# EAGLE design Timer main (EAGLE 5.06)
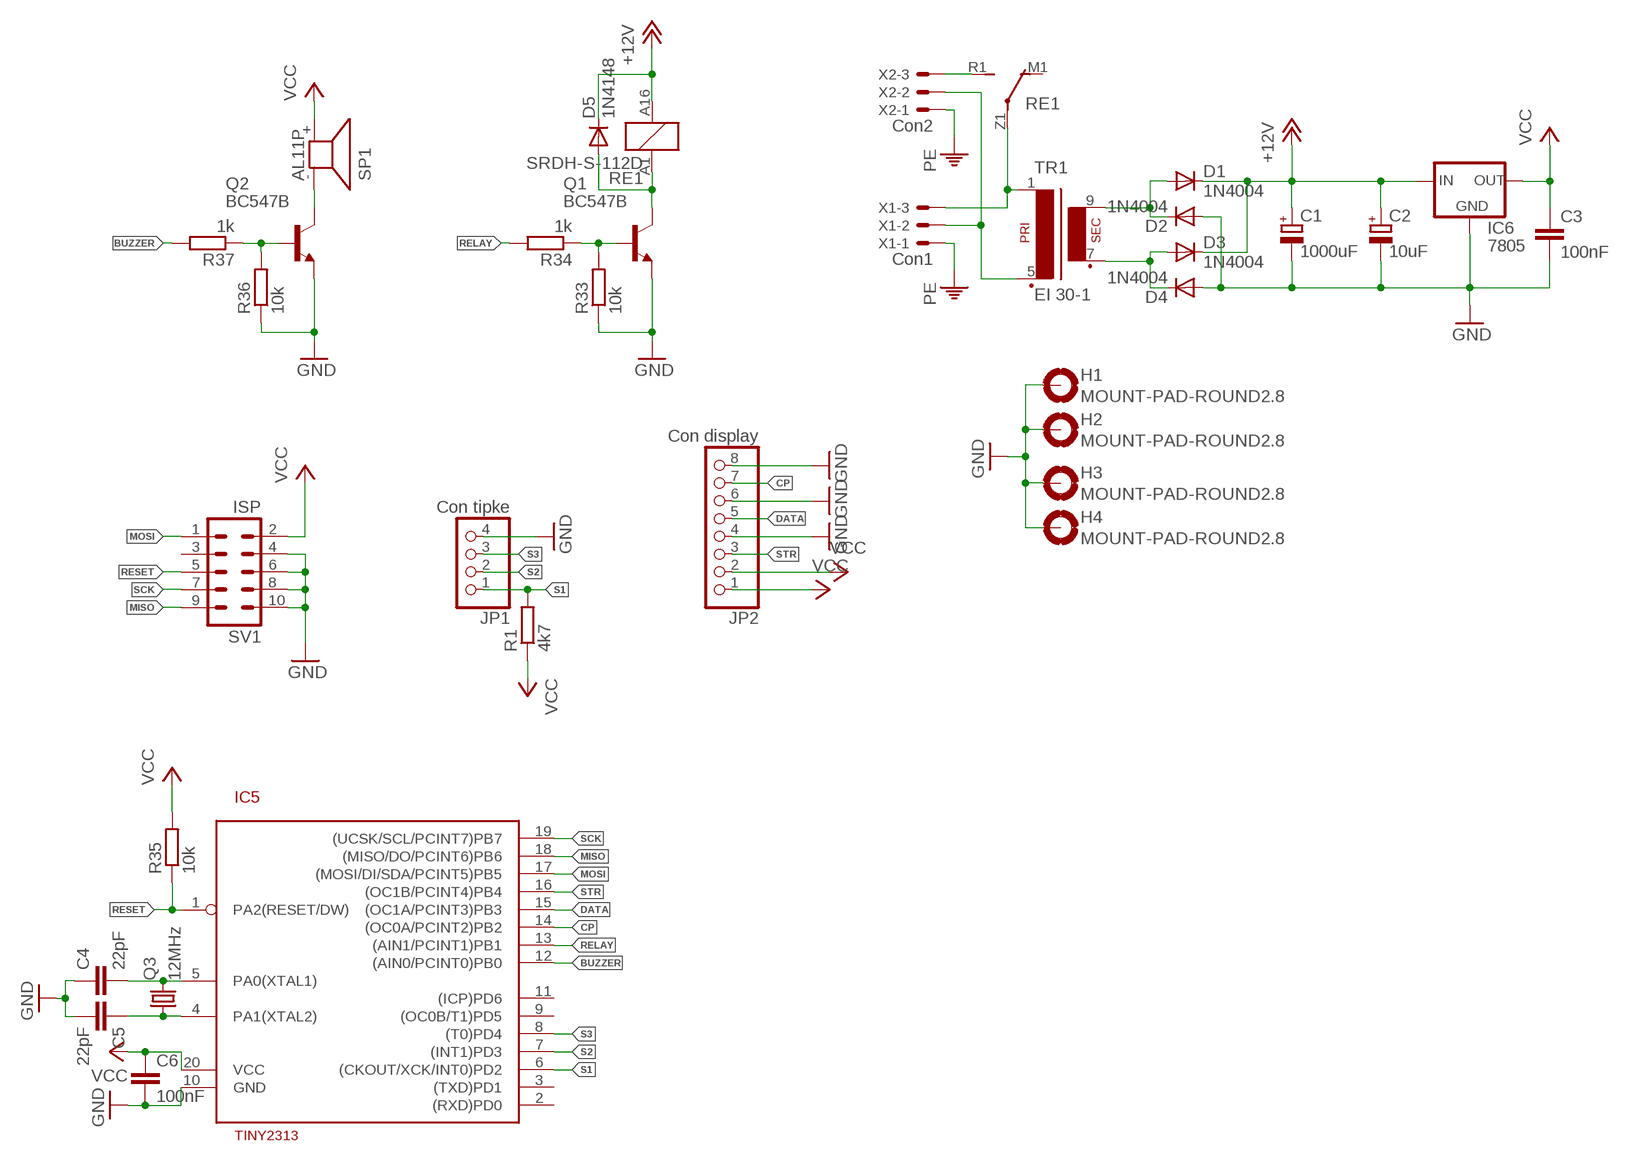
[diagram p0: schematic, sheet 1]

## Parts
C1  1000uF  CPOL-EUTT5D10  [TT5D10]
C2  10uF  CPOL-EUE2.5-5  [E2,5-5]
C3  100nF  C-EU050-025X075  [C050-025X075]
C4  22pF  C-EU025-025X050  [C025-025X050]
C5  22pF  C-EU025-025X050  [C025-025X050]
C6  100nF  C-EU050-025X075  [C050-025X075]
D1  1N4004  [DO41-10]
D2  1N4004  [DO41-10]
D3  1N4004  [DO41-10]
D4  1N4004  [DO41-10]
D5  1N4148  1N4148DO35-10  [DO35-10]
H1  MOUNT-PAD-ROUND2.8  [2,8-PAD]
H2  MOUNT-PAD-ROUND2.8  [2,8-PAD]
H3  MOUNT-PAD-ROUND2.8  [2,8-PAD]
H4  MOUNT-PAD-ROUND2.8  [2,8-PAD]
IC5  TINY2313  [DIL20]
IC6  7805  78XXL  [78XXL]
JP1  Con tipke  PINHD-1X4  [1X04]
JP2  Con display  PINHD-1X8  [1X08]
Q1  BC547B  [TO92]
Q2  BC547B  [TO92]
Q3  12MHz  CRYSTALHC49S  [HC49/S]
R1  4k7  R-EU_0207/10  [0207/10]
R33  10k  R-EU_0207/10  [0207/10]
R34  1k  R-EU_0207/10  [0207/10]
R35  10k  R-EU_0207/10  [0207/10]
R36  10k  R-EU_0207/10  [0207/10]
R37  1k  R-EU_0207/10  [0207/10]
RE1  SRDH-S-112D  [SRDH-S-112D]
SP1  AL11P  [AL11P]
SV1  ISP  ML10  [ML10]
TR1  EI 30-1  EI30-1-L  [SAMOZICE]
X1  Con1  KK-156-3  [KK-156-3]
X2  Con2  KK-156-3  [KK-156-3]

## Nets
+12V: C1.+ C2.+ D1.C D3.C D5.C IC6.IN RE1.A16
BUZZER: IC5.12((AIN0/PCINT0)PB0) R37.2
CP: IC5.14((OC0A/PCINT2)PB2) JP2.7
DATA: IC5.15((OC1A/PCINT3)PB3) JP2.5
GND: C1.- C2.- C3.2 C4.1 C5.2 C6.2 D2.A D4.A H1.B2,8(MOUNT) H2.B2,8(MOUNT) H3.B2,8(MOUNT) H4.B2,8(MOUNT) IC5.10(GND) IC6.GND JP1.4 JP2.4 JP2.6 JP2.8 Q1.1(E) Q2.1(E) R33.1 R36.1 SV1.4 SV1.6 SV1.8 SV1.10
MISO: IC5.18((MISO/DO/PCINT6)PB6) SV1.9
MOSI: IC5.17((MOSI/DI/SDA/PCINT5)PB5) SV1.1
N$65: RE1.Z1(P) TR1.1 X1.3
N$69: TR1.5(P2) X1.2 X2.2
N$70: D1.A D2.C TR1.9(S4)
N$71: D3.A D4.C TR1.7(S3)
N$72: RE1.R1(S) X2.3
N$73: Q1.2(B) R33.2 R34.1
N$74: D5.A Q1.3(C) RE1.A1
N$76: C4.2 IC5.5(PA0(XTAL1)) Q3.2
N$77: C5.1 IC5.4(PA1(XTAL2)) Q3.1
N$78: Q2.2(B) R36.2 R37.1
N$79: Q2.3(C) SP1.-
PE: X1.1 X2.1
RELAY: IC5.13((AIN1/PCINT1)PB1) R34.2
RESET: IC5.1(PA2(RESET/DW)) R35.1 SV1.5
S1: IC5.6((CKOUT/XCK/INT0)PD2) JP1.1 R1.2
S2: IC5.7((INT1)PD3) JP1.2
S3: IC5.8((T0)PD4) JP1.3
SCK: IC5.19((UCSK/SCL/PCINT7)PB7) SV1.7
STR: IC5.16((OC1B/PCINT4)PB4) JP2.3
VCC: C3.1 C6.1 IC5.20(VCC) IC6.OUT JP2.1 JP2.2 R1.1 R35.2 SP1.+ SV1.2
Unconnected: IC5.2((RXD)PD0) IC5.3((TXD)PD1) IC5.9((OC0B/T1)PD5) IC5.11((ICP)PD6) RE1.M1(O) SV1.3

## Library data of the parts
C1 C2 = resistor:CPOL-EU: POLARIZED CAPACITOR, European symbol
C3-C6 = resistor:C-EU: CAPACITOR, European symbol
D1-D4 = diode:1N4004: DIODE
D5 = diode:1N4148: DIODE
H1-H4 = holes:MOUNT-PAD-ROUND: MOUNTING PAD, round
IC5 = atmel:TINY2313: 2kB Flash, 20-pin
IC6 = v-reg:78XXL: VOLTAGE REGULATOR
JP1 = pinhead:PINHD-1X4: PIN HEADER
JP2 = pinhead:PINHD-1X8: PIN HEADER
Q1 Q2 = transistor-npn:BC547*: NPN Transistor
Q3 = crystal:CRYSTAL: CRYSTAL
R1 R33-R37 = resistor:R-EU_: RESISTOR, European symbol
RE1 = relay:SRDH-S-112D: 24V, 10A relay
SP1 = buzzer:AL11P: SPEAKER
SV1 = con-harting-ml:ML10: HARTING
TR1 = trafo:EI30-1: TRANSFORMER 1 primary winding, 1 secondary winding ERA
X1 X2 = con-molex:KK-156-3: KK 156 HEADER Source: http://www.molex.com/pdm_docs/sd/026604100_sd.pdf

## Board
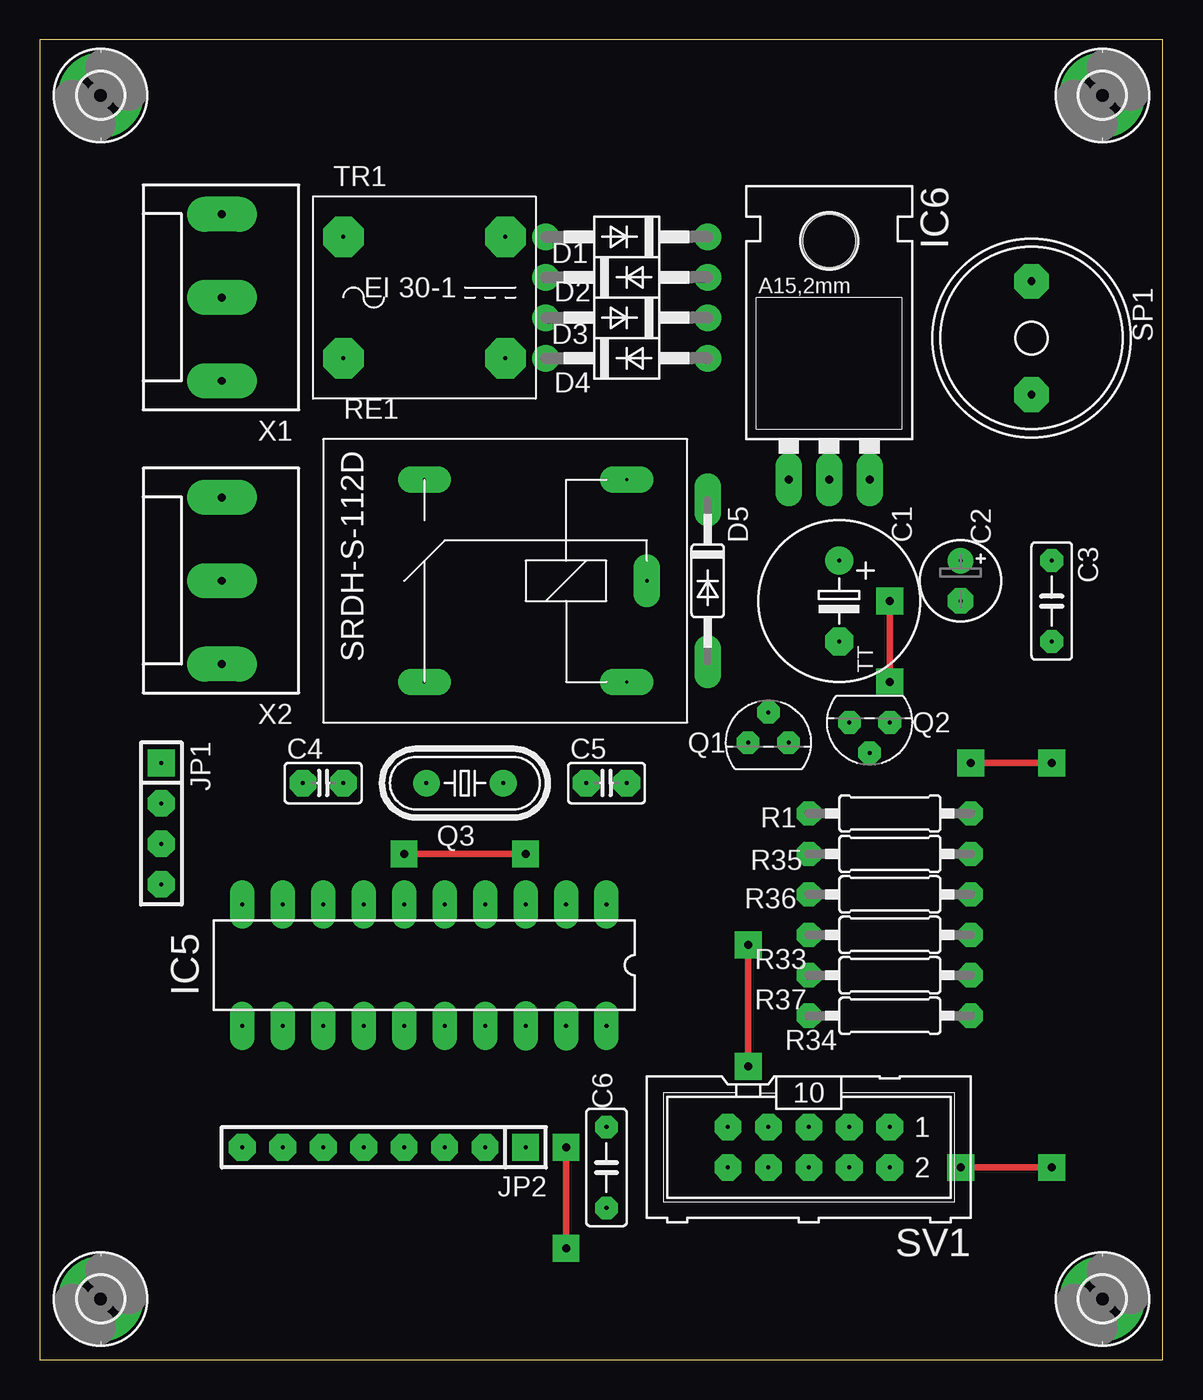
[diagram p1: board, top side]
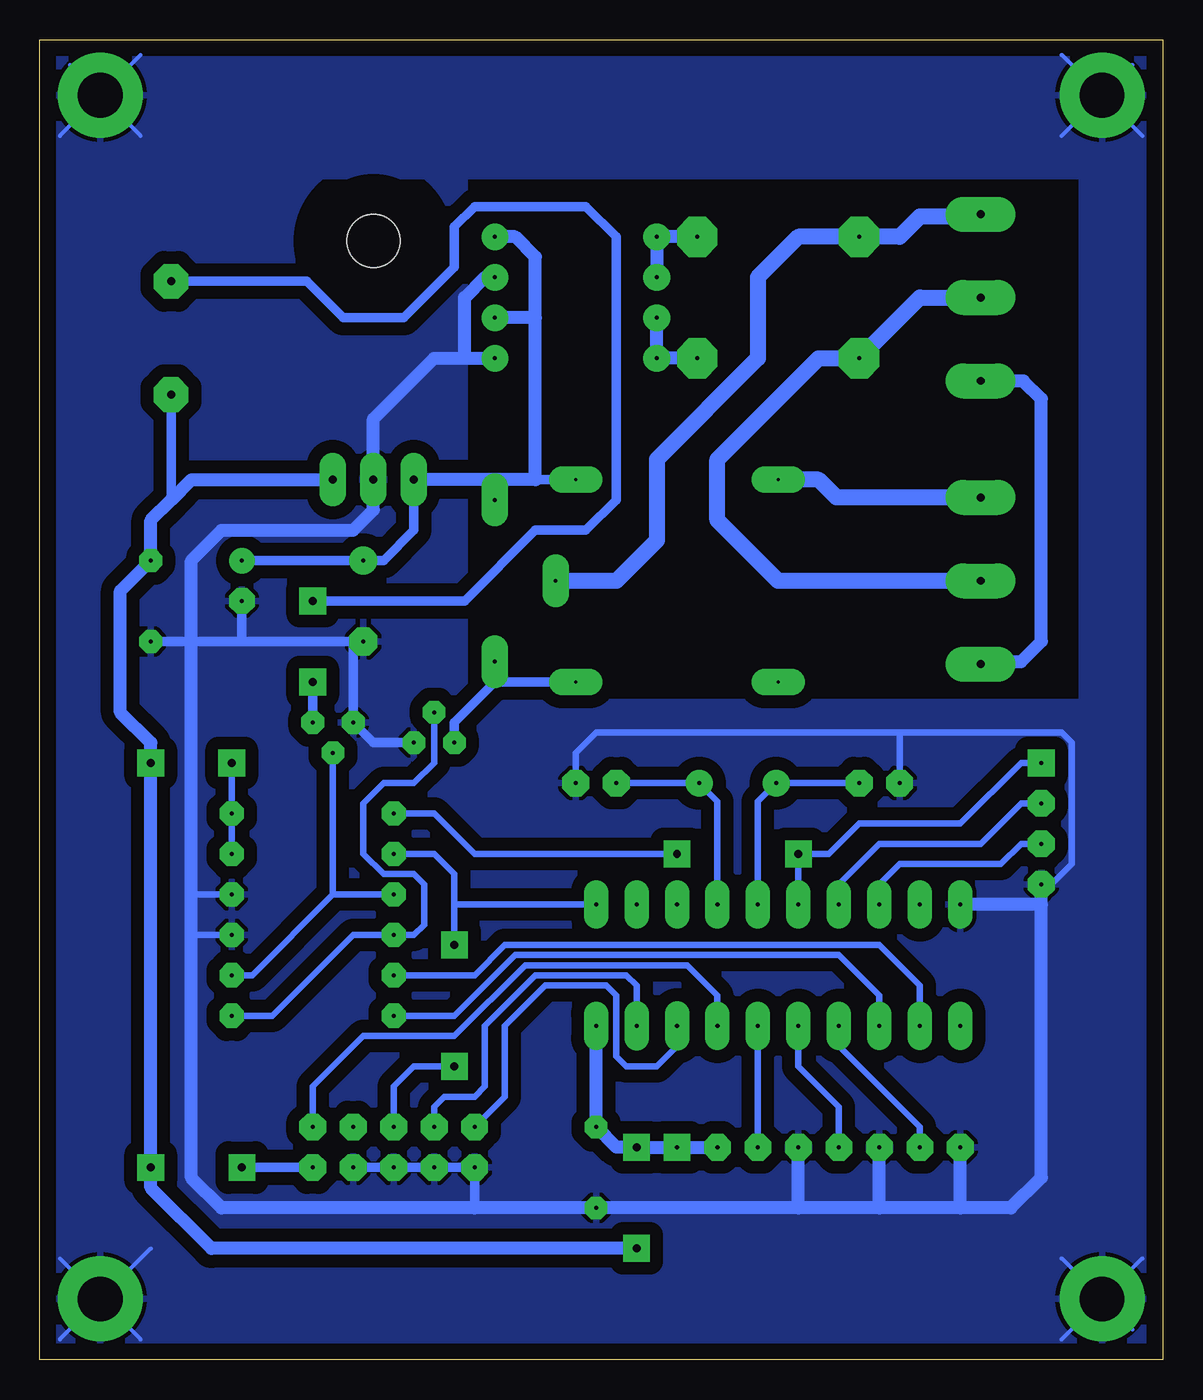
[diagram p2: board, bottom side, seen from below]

Size 70.47 x 82.85 mm. Coordinates in mm from the lower left corner, seen from the top.
Outline: 0,0 70.47,0 70.47,82.85 0,82.85 0,0
Copper layers (1*16): Top 0.035mm / dielectric 1.5mm / Bottom 0.035mm
Design rules "default *": minimum track width 16mil, minimum drill 1mil, track to track 8mil, track to pad 8mil, pad to pad 8mil, via to via 8mil, smd to smd 8mil, copper to edge 40mil, drill to drill 8mil, minimum pad ring 10mil, minimum via ring 8mil, stop-mask expansion 4mil, vias tented up to drill 0mil, thermal gap 10mil

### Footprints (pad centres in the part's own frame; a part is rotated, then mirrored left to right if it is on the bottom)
TT5D10 = drill 0.254 pad 1.778 round: + -2.54,0 | drill 0.254 pad 1.778 octagon: - 2.54,0
E2,5-5 = drill 0.254 pad 1.6 round: + -1.27,0 | drill 0.254 pad 1.6 octagon: - 1.27,0
C050-025X075 = drill 0.254 pad 1.422 octagon: 1 -2.54,0; 2 2.54,0
C025-025X050 = drill 0.254 pad 1.676 octagon: 1 -1.27,0; 2 1.27,0
DO41-10 = drill 0.254 pad 1.676 round: A 5.08,0; C -5.08,0
DO35-10 = drill 0.254 pad 1.676 long: A 5.08,0; C -5.08,0
2,8-PAD = drill 2.8 pad 5.334 round: B2,8 0,0
DIL20 = drill 0.254 pad 1.524 long: 1 -11.43,-3.81; 2 -8.89,-3.81; 3 -6.35,-3.81; 4 -3.81,-3.81; 5 -1.27,-3.81; 6 1.27,-3.81; 7 3.81,-3.81; 8 6.35,-3.81; 9 8.89,-3.81; 10 11.43,-3.81; 11 11.43,3.81; 12 8.89,3.81; 13 6.35,3.81; 14 3.81,3.81; 15 1.27,3.81; 16 -1.27,3.81; 17 -3.81,3.81; 20 -11.43,3.81 | drill 0.254 pad 1.549 long: 18 -6.35,3.81; 19 -8.89,3.81
78XXL = drill 0.5 pad 1.676 long: GND 0,-3.81; IN -2.54,-3.81; OUT 2.54,-3.81 | hole 3.302: 0,11.176
1X04 = drill 0.254 pad 1.676 square: 1 -3.81,0 | drill 0.254 pad 1.676 octagon: 2 -1.27,0; 3 1.27,0; 4 3.81,0
1X08 = drill 0.254 pad 1.676 square: 1 -8.89,0 | drill 0.254 pad 1.676 octagon: 2 -6.35,0; 3 -3.81,0; 4 -1.27,0; 5 1.27,0; 6 3.81,0; 7 6.35,0; 8 8.89,0
TO92 = drill 0.254 pad 1.422 octagon: 1 1.27,0; 2 0,1.905; 3 -1.27,0
HC49/S = drill 0.254 pad 1.676 round: 1 -2.413,0; 2 2.413,0
0207/10 = drill 0.254 pad 1.524 octagon: 1 -5.08,0; 2 5.08,0
SRDH-S-112D = drill 0.2 pad 1.676 long: A1 6.35,-6.35; A16 6.35,6.35; M1 -6.35,-6.35; R1 -6.35,6.35; Z1 7.62,0
AL11P = drill 0.5 pad 2.184 octagon: + 3.556,0; - -3.556,0
ML10 = drill 0.254 pad 1.676 octagon: 1 -5.08,-1.27; 2 -5.08,1.27; 3 -2.54,-1.27; 4 -2.54,1.27; 5 0,-1.27; 6 0,1.27; 7 2.54,-1.27; 8 2.54,1.27; 9 5.08,-1.27; 10 5.08,1.27
SAMOZICE = drill 0.254 pad 2.54 octagon: 1 -5.08,3.81; 5 -5.08,-3.81; 7 5.08,-3.81; 9 5.08,3.81
KK-156-3 = drill 0.5 pad 2.184 long: 1 -5.23,0; 2 0,0; 3 5.23,0

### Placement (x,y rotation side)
C1  50.16,47.62 270 top
C2  57.78,48.89 270 top
C3  63.5,47.62 270 top
C4  17.78,36.19 0 top
C5  35.56,36.19 0 top
C6  35.56,12.07 270 top
D1  36.83,70.48 180 top
D2  36.83,67.94 0 top
D3  36.83,65.41 180 top
D4  36.83,62.86 0 top
D5  41.91,48.89 270 top
H1  3.81,3.81 0 top
H2  66.67,3.81 0 top
H3  3.81,79.38 0 top
H4  66.67,79.38 0 top
IC5  24.13,24.76 180 top
IC6  49.53,59.05 0 top
JP1  7.62,33.66 270 top
JP2  21.59,13.34 180 top
Q1  45.72,38.73 0 top
Q2  52.07,40 180 top
Q3  26.67,36.19 180 top
R1  53.34,34.29 180 top
R33  53.34,26.67 180 top
R34  53.34,21.59 180 top
R35  53.34,31.75 0 top
R36  53.34,29.21 180 top
R37  53.34,24.13 180 top
RE1  30.48,48.89 0 top
SP1  62.23,64.13 270 top
SV1  48.26,13.34 180 top
TR1  24.13,66.67 0 top
X1  11.43,66.67 90 top
X2  11.43,48.89 90 top

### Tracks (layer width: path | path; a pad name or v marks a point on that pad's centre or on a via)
+12V
  Bottom 0.61: C2.+ C1.+ 48.9,50.16 46.99,52.07 IC6.IN | RE1.A16 39.37,55.24 | 41.91,55.24 D5.C
  Bottom 0.813: 39.37,65.41 39.37,69.21 40.64,70.48 D1.C | 39.37,65.41 D3.C | 39.37,65.41 39.37,55.24 41.91,55.24 IC6.IN
BUZZER
  Bottom 0.406: IC5.12 15.24,23.5 17.78,26.04 41.27,26.04 43.18,24.13 R37.2
CP
  Bottom 0.406: IC5.14 20.32,19.68 15.24,14.61 JP2.7
DATA
  Bottom 0.406: IC5.15 22.86,18.42 20.32,15.88 JP2.5
GND
  Bottom 0.254: H4.B2,8 68.58,81.28 | 64.14,76.83 H4.B2,8 | H4.B2,8 64.14,81.91 | H4.B2,8 69.22,76.83 | 1.27,6.35 6.35,1.27 | 1.91,1.91 6.35,6.35 | 1.27,76.83 6.35,81.91 | 1.91,81.28 6.35,76.83 | 69.22,1.27 63.5,6.98 | 64.14,1.27 69.22,6.35
  Bottom 0.406: 16.51,39.37 6.35,39.37 5.71,38.73 5.71,31.11 6.99,29.85 JP1.4 | 16.51,39.37 35.56,39.37 36.83,38.1 C5.2 | 16.51,39.37 C4.1 | 60.96,29.21 R36.1 | 60.96,26.67 R33.1
  Bottom 0.61: 57.78,45.08 50.8,45.08 Q2.1 49.53,38.73 Q1.1 | 57.78,45.08 60.96,45.08 C3.2 | SV1.4 SV1.6 SV1.8 SV1.10 43.18,9.52 | 57.78,45.08 C2.-
  Bottom 0.813: 43.81,62.86 45.72,62.86 49.53,59.05 IC6.GND 49.53,53.34 50.8,52.07 59.05,52.07 60.96,50.16 60.96,45.08 60.96,29.21 60.96,26.67 60.96,11.43 59.05,9.52 43.18,9.52 C6.2 22.86,9.52 | 43.81,62.86 D4.A | D2.A 42.55,67.94 43.81,66.67 43.81,62.86 | 50.8,45.08 C1.- | 7.62,28.57 7.62,11.43 9.53,9.52 12.7,9.52 | 7.62,28.57 JP1.4 | 12.7,9.52 17.78,9.52 | 17.78,9.52 22.86,9.52 | 22.86,9.52 JP2.4 | 17.78,9.52 JP2.6 | 12.7,9.52 JP2.8 | 7.62,28.57 IC5.10
  pour Bottom: 0,41.28 0,82.55 70.48,82.55 70.48,74.3 5.08,74.3 5.08,41.28
  pour Bottom (isolate 0.813): 0,41.28 43.81,41.28 43.81,74.3 70.48,74.3 70.48,0 0,0
MISO
  Bottom 0.406: IC5.18 30.48,19.68 31.75,18.42 33.66,18.42 34.29,19.05 34.29,22.86 34.92,23.5 38.73,23.5 41.27,20.96 41.27,16.51 SV1.9
MOSI
  Bottom 0.406: IC5.17 27.94,22.86 29.84,24.76 40.01,24.76 44.45,20.32 50.16,20.32 53.34,17.14 SV1.1
N$65
  Bottom 1.016: RE1.Z1 34.29,48.89 31.75,51.44 31.75,56.52 25.4,62.86 25.4,67.94 22.86,70.48 TR1.1 16.51,70.48 15.24,71.75 11.58,71.75 X1.3
N$69
  Bottom 1.016: X2.2 24.13,48.89 27.94,52.7 27.94,56.52 21.59,62.86 TR1.5 15.24,66.67 X1.2
N$70
  Bottom 0.813: TR1.9 D1.A D2.C
N$71
  Bottom 0.813: TR1.7 D4.C D3.A
N$72
  Bottom 1.016: X2.3 20.47,54.12 21.59,55.24 RE1.R1
N$73
  Bottom 0.406: Q1.2 45.72,37.47 46.99,36.19 48.9,36.19 50.16,34.92 50.16,31.75 48.9,30.48 46.99,30.48 46.35,29.85 46.35,27.3 46.99,26.67 R33.2 50.8,26.67 55.88,21.59 R34.1
N$74
  Bottom 0.61: RE1.A1 41.91,42.55 | 41.91,42.55 D5.A | 41.91,42.55 44.45,40 Q1.3
N$76
  Bottom 0.406: C4.2 Q3.2 25.4,35.05 IC5.5
N$77
  Bottom 0.406: C5.1 Q3.1 27.94,35.05 IC5.4
N$78
  Bottom 0.406: 52.07,29.21 Q2.2 | 52.07,29.21 57.15,24.13 R37.1 | R36.2 52.07,29.21
N$79  (via drill 0.5 pad 1.68)
  Top 0.406: v53.34,47.62 v53.34,42.55
  Bottom 0.61: v53.34,42.55 Q2.3 | SP1.- 53.72,67.69 51.44,65.41 47.62,65.41 44.45,68.58 44.45,71.12 43.18,72.39 36.2,72.39 34.29,70.48 34.29,53.97 36.2,52.07 39.37,52.07 43.81,47.62 v53.34,47.62
PE
  Bottom 0.813: X1.1 8.74,61.44 7.62,60.33 7.62,45.08 8.89,43.81 11.28,43.81 X2.1
RELAY
  Bottom 0.406: IC5.13 17.78,22.86 20.32,25.4 40.64,25.4 44.45,21.59 R34.2
RESET  (via drill 0.5 pad 1.68)
  Top 0.406: v44.45,18.42 v44.45,26.04
  Bottom 0.406: R35.1 45.72,31.75 44.45,30.48 44.45,28.57 | v44.45,26.04 44.45,28.57 | 44.45,28.57 IC5.1 | SV1.5 48.26,17.14 46.99,18.42 v44.45,18.42
S1  (via drill 0.5 pad 1.68)
  Top 0.406: v22.86,31.75 v30.48,31.75
  Bottom 0.406: JP1.1 8.89,37.47 12.7,33.66 19.05,33.66 20.95,31.75 v22.86,31.75 IC5.6 | v30.48,31.75 43.18,31.75 45.72,34.29 R1.2
S2
  Bottom 0.406: JP1.2 8.89,34.92 11.43,32.39 17.78,32.39 20.32,29.85 IC5.7
S3
  Bottom 0.406: JP1.3 8.89,32.39 10.16,31.11 16.51,31.11 17.78,29.85 IC5.8
SCK
  Bottom 0.406: IC5.19 33.02,23.5 33.66,24.13 39.37,24.13 42.55,20.96 42.55,17.14 43.18,16.51 45.09,16.51 45.72,15.88 SV1.7
STR
  Bottom 0.406: JP2.3 IC5.16
VCC  (via drill 0.5 pad 1.68)
  Top 0.406: v33.02,6.98 v33.02,13.34 | v63.5,37.47 v58.42,37.47 | v63.5,12.07 v57.78,12.07
  Bottom 0.406: R35.2 R1.1 v58.42,37.47
  Bottom 0.61: 62.23,53.97 SP1.+ | v57.78,12.07 SV1.2
  Bottom 0.813: IC5.20 C6.1 34.29,13.34 v33.02,13.34 JP2.1 JP2.2 | v33.02,6.98 59.69,6.98 63.5,10.79 v63.5,12.07 v63.5,37.47 63.5,38.73 65.41,40.64 65.41,48.26 C3.1 63.5,52.7 62.23,53.97 60.96,55.24 IC6.OUT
